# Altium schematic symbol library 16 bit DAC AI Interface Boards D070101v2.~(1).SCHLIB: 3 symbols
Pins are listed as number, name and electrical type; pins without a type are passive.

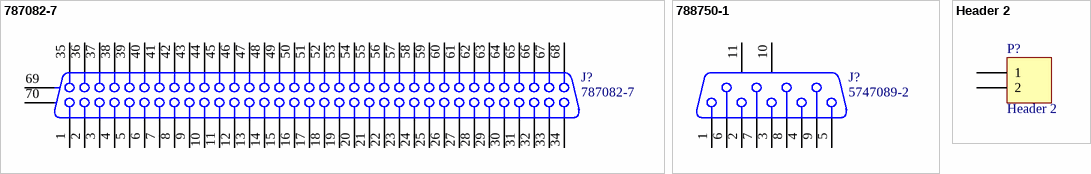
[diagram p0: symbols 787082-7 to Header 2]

## 787082-7
designator J?
Receptacle Assembly, Shielded, Right Angle, AMPLIMITE; Manufacturer: TE Connectivity; Description: CONN D-TYPE RCPT 68POS R/A SLDR; Plating: Bright,Copper; Voltage Rating: 30V; Current Rating: 1A; Gender: Female; Number of Positions: 68; Connector Type: Receptacle,Connector; Number of Ports: 1; Mating Alignment: No (Without); Mating Connector Lock: Yes (With); PCB Mount Retention: With; Pitch: 0.05inch; PCB Thickness: 1.57mm; Contact Post Length: 0.1inch; Hole Diameter: 0.109inch; Approvals: UL
footprint 787082-7 (Connector; D Subminiature 050 Series; 68 Position; Right Angle)
signal-integrity model D Subminiature
pins: 1, 2, 3, 4, 5, 6, 7, 8, 9, 10, 11, 12, 13, 14, 15, 16, 17, 18, 19, 20, 21, 22, 23, 24, 25, 26, 27, 28, 29, 30, 31, 32, 33, 34, 35, 36, 37, 38, 39, 40, 41, 42, 43, 44, 45, 46, 47, 48, 49, 50, 51, 52, 53, 54, 55, 56, 57, 58, 59, 60, 61, 62, 63, 64, 65, 66, 67, 68, 69 MH1, 70 MH2

## 788750-1
designator J?, comment 5747089-2
Receptacle Assembly, 9 Position, Right Angle, 8.08mm Series, Amplimite; Manufacturer: TE Connectivity; Manufacturer Part Number: 5747844-4; Description: D Sub Connector, Amplimite Hd-20, Amplimite Hd-20 Series, De, Receptacle, 9, Metal, Solder; Plating: Tin; Body Material: Metal; Gender: Female; Voltage Rating: 125V; Current Rating: 6A; Number of Positions: 9; Number of Ports: 1; Mating Connector Lock: Yes (With); Preloaded: Yes; PCB Mount Retention: With; Sealable: No (Without); Pitch: 0.108inch; PCB Thickness: 1.58mm; Contact Post Length: 0.125inch; Hole Diameter: 3.18mm; Approvals: UL,CSA
footprint 788750-1 (Connector; D Subminiature AMPLIMITE 2000; 9 Position; Right Angle)
signal-integrity model D Subminiature
footprint DB9/F
pins: 1, 2, 3, 4, 5, 6, 7, 8, 9, 10 MH1, 11 MH2

## Header 2
designator P?
Header, 2-Pin; Manufacturer: Molex; Description: Wire-To-Board Connector, KK 6373 Series, Through Hole, Header, 2, 2.54 mm, Tin Plated Contacts; Number of Positions: 2; Gender: Male; Contact Resistance: 10mR; Max Current Rating: 4A; Voltage Rating: 250V; Insulation Resistance: 500GR; Pitch: 2.54mm; Approvals: UL,CSA; Glow Wire Compliant: Non-compliant
footprint HDR1X2 (Connector; Header; 2 Position)
signal-integrity model Connector
pins: 1, 2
